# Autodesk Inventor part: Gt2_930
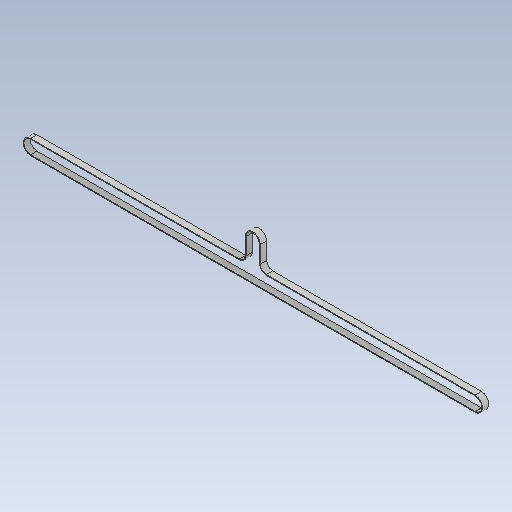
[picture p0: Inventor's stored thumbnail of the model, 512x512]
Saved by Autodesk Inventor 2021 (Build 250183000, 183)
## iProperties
Created: 2026-10
Part Number: Gt2_930
Material: Steel
Document SubType Name: Modeling
Designer: hp
Density: 7.85 g/cm^3
Appearance: Default
Author: hp
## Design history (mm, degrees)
feature "Body1"
body "Solid1"
